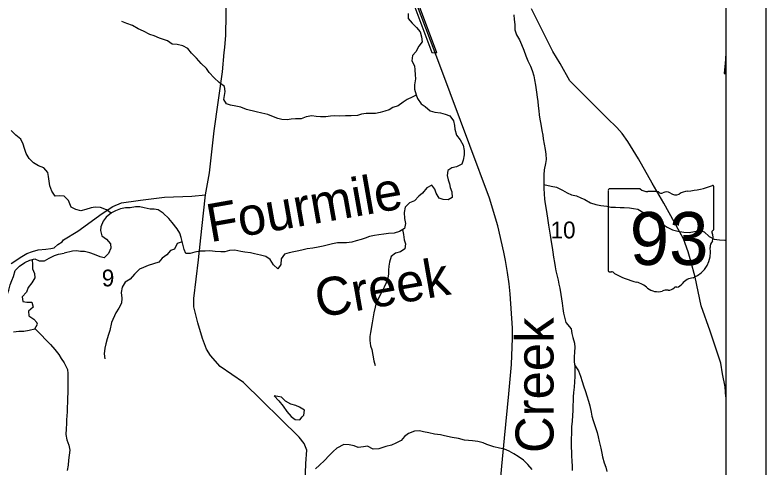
# Model space of a CAD drawing. Extents: x 0 to 34, y 0 to 22.
# Drawn here: x 7.127 to 9, y 17.601 to 18.731 of the extents above; entities that cross this region are included whole.
import ezdxf

# ---------------------------------------------------------------- set-up
doc = ezdxf.new("R2010")
doc.units = 0
for name, color, linetype in [('GM_X_Corporation', 7, 'Continuous'), ('GM_X_County_Road', 7, 'Continuous'), ('GM_X_Major_River', 7, 'Continuous'), ('GM_X_Major_River_Text', 7, 'Continuous'), ('GM_X_Minor_Lake', 7, 'Continuous'), ('GM_X_Minor_River', 7, 'Continuous'), ('GM_X_Minor_River_Text', 7, 'Continuous'), ('GM_X_Rail_Line', 7, 'Continuous'), ('GM_X_Section_Text', 7, 'Continuous'), ('GM_X_State_Location', 7, 'Continuous'), ('GM_X_State_Route', 7, 'Continuous'), ('GM_X_State_Shield', 7, 'Continuous'), ('SH_Data', 7, 'Continuous')]:
    doc.layers.add(name, color=color, linetype=linetype)

msp = doc.modelspace()

# ---------------------------------------------------------------- linework, layer by layer
at = {"layer": 'GM_X_Corporation'}
msp.add_lwpolyline([(7.8422, 19.5022), (8.1668, 18.6372), (8.1793, 18.6363), (7.8577, 19.4956)], dxfattribs=at)
msp.add_lwpolyline([(8.9, 18.5845), (8.9, 18.6278), (8.8955, 18.5848)], close=True, dxfattribs=at)
at = {"layer": 'GM_X_County_Road'}
for points in [[(7.602, 18.2822), (7.6125, 18.3372), (7.6238, 18.442), (7.645, 18.589), (7.649, 18.6371), (7.6503, 18.6497), (7.653, 18.6804), (7.6556, 18.8319), (7.6532, 18.948)], [(7.1177, 18.1111), (7.1444, 18.1289), (7.1563, 18.1363), (7.1707, 18.1413), (7.1846, 18.1452), (7.2043, 18.1471), (7.2167, 18.1482), (7.2244, 18.1498), (7.2341, 18.1583), (7.2444, 18.1648), (7.2479, 18.1697), (7.284, 18.1921), (7.3442, 18.2355), (7.3709, 18.2535), (7.3929, 18.2623), (7.4342, 18.268), (7.4401, 18.2692), (7.4996, 18.2765), (7.5683, 18.279), (7.602, 18.2822)], [(7.851, 17.564), (7.8526, 17.6125), (7.8548, 17.6459), (7.8483, 17.6625), (7.8357, 17.678), (7.6971, 17.8144), (7.6392, 17.8541), (7.6151, 17.8814), (7.6049, 17.8978), (7.5951, 17.9238), (7.5832, 17.9628), (7.5728, 18.0032), (7.5728, 18.024), (7.5845, 18.1204), (7.5932, 18.1984), (7.602, 18.2822)]]:
    msp.add_lwpolyline(points, dxfattribs=at)
at = {"layer": 'GM_X_Major_River'}
for points in [[(8.371, 18.7312), (8.3721, 18.7198), (8.3735, 18.7069), (8.3734, 18.694), (8.3778, 18.6814), (8.3849, 18.6684), (8.3905, 18.657), (8.3957, 18.6426), (8.4012, 18.6292), (8.4064, 18.6167), (8.4124, 18.6033), (8.4169, 18.5919), (8.4209, 18.5786), (8.4223, 18.5691), (8.4249, 18.5558), (8.4278, 18.5383)], [(8.4278, 18.5383), (8.4296, 18.5262), (8.431, 18.5148), (8.432, 18.5042), (8.4334, 18.492), (8.4345, 18.4818), (8.4363, 18.4707), (8.4388, 18.4582), (8.4414, 18.443), (8.4432, 18.4312), (8.4446, 18.4217), (8.4471, 18.4088), (8.4497, 18.3951), (8.4511, 18.3841), (8.4514, 18.3704), (8.4501, 18.3606), (8.4466, 18.3447), (8.4457, 18.3325), (8.446, 18.3215), (8.4459, 18.3105), (8.4462, 18.2984), (8.4465, 18.2847), (8.4479, 18.2711), (8.4497, 18.2597), (8.4522, 18.2456), (8.4536, 18.2353), (8.4551, 18.224), (8.4576, 18.2069), (8.459, 18.1966), (8.4619, 18.1814), (8.4637, 18.1708), (8.4655, 18.1605), (8.467, 18.151), (8.4687, 18.1392), (8.4705, 18.1267), (8.4723, 18.1134), (8.4741, 18.1031), (8.4763, 18.0925), (8.4796, 18.0792), (8.4814, 18.0693), (8.4836, 18.0598), (8.4858, 18.0495), (8.4883, 18.0336), (8.4897, 18.023), (8.4916, 18.0123), (8.4937, 17.9986), (8.4951, 17.9869), (8.4973, 17.977), (8.5006, 17.9641)], [(8.5006, 17.9641), (8.5144, 17.9478), (8.5158, 17.9368), (8.5184, 17.9265), (8.5228, 17.9124), (8.5231, 17.9018), (8.5222, 17.8912), (8.5213, 17.8779), (8.5216, 17.8662), (8.523, 17.8548), (8.5237, 17.8423), (8.5235, 17.829), (8.5227, 17.8158), (8.5214, 17.8025), (8.5202, 17.7896), (8.5193, 17.779), (8.5189, 17.7695), (8.5187, 17.7559), (8.5183, 17.7445), (8.5178, 17.732), (8.5169, 17.7184), (8.5153, 17.7036), (8.5148, 17.6888), (8.5142, 17.6725), (8.5144, 17.6532), (8.5147, 17.6403), (8.515, 17.6304), (8.5157, 17.6194), (8.5163, 17.6046), (8.5166, 17.5948)]]:
    msp.add_lwpolyline(points, dxfattribs=at)
at = {"layer": 'GM_X_Minor_Lake'}
for points in [[(7.7735, 17.7812), (7.7849, 17.769), (7.7958, 17.7554), (7.8049, 17.7425), (7.8155, 17.73), (7.8261, 17.7224), (7.8374, 17.7217), (7.8434, 17.7284)], [(7.8434, 17.7284), (7.8476, 17.733), (7.8495, 17.7452), (7.837, 17.7531), (7.8272, 17.7573), (7.8151, 17.7603), (7.8019, 17.7679), (7.7917, 17.7781), (7.7735, 17.7812)]]:
    msp.add_lwpolyline(points, dxfattribs=at)
at = {"layer": 'GM_X_Minor_River'}
for points in [[(8.1075, 18.7348), (8.1078, 18.7223), (8.1176, 18.7105), (8.1285, 18.6998), (8.1376, 18.6884), (8.1413, 18.6759), (8.1428, 18.6641), (8.1341, 18.6528), (8.1264, 18.6392), (8.1188, 18.6293), (8.1169, 18.6168), (8.1233, 18.6039), (8.124, 18.5937), (8.1255, 18.5815), (8.1258, 18.5713), (8.1235, 18.5569), (8.1231, 18.5459), (8.1272, 18.5318), (8.131, 18.5223), (8.14, 18.5094), (8.1502, 18.5026), (8.1623, 18.4915), (8.1744, 18.4881), (8.188, 18.4865), (8.2001, 18.4834), (8.2118, 18.4792), (8.2205, 18.4671), (8.2235, 18.4553), (8.2242, 18.4458), (8.2283, 18.431), (8.2373, 18.4196), (8.2452, 18.4063), (8.2475, 18.393), (8.2474, 18.382), (8.2451, 18.3688), (8.2413, 18.3585), (8.2284, 18.3521), (8.2167, 18.3495), (8.2064, 18.3427), (8.2045, 18.3302), (8.2075, 18.3196), (8.2105, 18.3101), (8.2127, 18.3006), (8.2168, 18.2896), (8.2172, 18.2759), (8.2073, 18.2699), (8.1948, 18.2703), (8.185, 18.2738), (8.1771, 18.2867), (8.1745, 18.2962), (8.1666, 18.3068), (8.1544, 18.3), (8.1438, 18.2868), (8.1343, 18.2792), (8.1237, 18.2675), (8.1108, 18.2623), (8.1005, 18.2513), (8.0974, 18.238), (8.0989, 18.2232), (8.1011, 18.2107), (8.0981, 18.1986), (8.0859, 18.191), (8.0727, 18.1869), (8.0583, 18.1858), (8.0473, 18.1844), (8.0344, 18.1825), (8.0238, 18.1806), (8.0109, 18.1784), (8.0007, 18.1739), (7.9905, 18.1713), (7.978, 18.1679), (7.9674, 18.1645), (7.9541, 18.1623), (7.9424, 18.1623), (7.9318, 18.1627), (7.9189, 18.1598), (7.9091, 18.1575), (7.8954, 18.1541), (7.8829, 18.1515), (7.8701, 18.1493), (7.8557, 18.1475), (7.8458, 18.1452), (7.8348, 18.143), (7.8223, 18.14), (7.811, 18.1377)], [(8.1275, 18.5312), (8.1177, 18.5262), (8.1052, 18.5198), (8.0954, 18.513), (8.0828, 18.5043), (8.0696, 18.4998), (8.0601, 18.4945), (8.0495, 18.4911), (8.0381, 18.4878), (8.026, 18.4848), (8.0131, 18.4852), (8.0025, 18.4852), (7.9912, 18.4838), (7.9809, 18.4804), (7.9658, 18.4793), (7.951, 18.4793), (7.9374, 18.4786), (7.9238, 18.4791), (7.9136, 18.4787), (7.9026, 18.4772), (7.889, 18.4765), (7.878, 18.4777), (7.867, 18.4792), (7.853, 18.4766), (7.8409, 18.4718), (7.8265, 18.4714), (7.8159, 18.4711), (7.8061, 18.4696), (7.7924, 18.4704), (7.7826, 18.4727), (7.7716, 18.4765), (7.7577, 18.4823), (7.7429, 18.4861), (7.7289, 18.4892), (7.7047, 18.4953), (7.69, 18.5011), (7.6775, 18.503), (7.6643, 18.5057), (7.6544, 18.5088), (7.6477, 18.5198), (7.6492, 18.53), (7.6511, 18.5399), (7.6493, 18.552), (7.6361, 18.5627), (7.6236, 18.5741), (7.6116, 18.5874), (7.6048, 18.5977), (7.5916, 18.6099), (7.5799, 18.6228), (7.5671, 18.6357), (7.5584, 18.6475), (7.5459, 18.6536), (7.5319, 18.6571), (7.5187, 18.6579), (7.5078, 18.6659), (7.4972, 18.6697), (7.4873, 18.6732), (7.4741, 18.6785), (7.4631, 18.682), (7.448, 18.6904), (7.4341, 18.6965), (7.4201, 18.7041), (7.4061, 18.7099), (7.3932, 18.7141)], [(7.25, 18.2789), (7.2391, 18.2801), (7.2277, 18.279), (7.2187, 18.2916), (7.2139, 18.3045), (7.2121, 18.3163), (7.211, 18.3281), (7.2088, 18.3379), (7.1991, 18.3494), (7.1858, 18.3548), (7.173, 18.3621), (7.1625, 18.3731), (7.155, 18.3853), (7.1509, 18.3975), (7.1476, 18.4085), (7.1413, 18.4211), (7.1296, 18.431), (7.1176, 18.4428)], [(8.446, 18.3083), (8.464, 18.3043), (8.4773, 18.3012), (8.4924, 18.2943), (8.5045, 18.2875), (8.515, 18.2825), (8.5275, 18.2798), (8.5381, 18.2748), (8.5479, 18.2703), (8.5623, 18.2622), (8.5755, 18.2584), (8.5884, 18.2561), (8.6031, 18.2538), (8.6133, 18.2518), (8.6247, 18.2518), (8.636, 18.251), (8.6462, 18.2506), (8.6595, 18.2502), (8.6693, 18.2482), (8.6803, 18.2463), (8.6954, 18.2371), (8.7098, 18.2299), (8.7237, 18.2215), (8.7385, 18.212), (8.7536, 18.2017), (8.7668, 18.1952), (8.7804, 18.1917), (8.7952, 18.1894), (8.8088, 18.1886), (8.8217, 18.1912), (8.8353, 18.1934), (8.8455, 18.19), (8.8579, 18.1786), (8.8708, 18.1717), (8.8844, 18.1698), (8.8976, 18.169), (8.9, 18.1696)], [(7.367, 18.2362), (7.3553, 18.2451), (7.3402, 18.2505), (7.3273, 18.2516), (7.3171, 18.2502), (7.3038, 18.246), (7.2913, 18.2427), (7.2792, 18.2461), (7.2675, 18.2515), (7.2604, 18.2685), (7.25, 18.2789)], [(7.811, 18.1377), (7.7996, 18.1344), (7.7912, 18.1226), (7.7897, 18.109), (7.7828, 18.0976), (7.7715, 18.1075), (7.7632, 18.1208), (7.7527, 18.1288), (7.7391, 18.1319), (7.7247, 18.135), (7.7145, 18.1377), (7.7005, 18.1393), (7.6906, 18.1412), (7.6751, 18.1443), (7.6623, 18.1439), (7.6505, 18.1406), (7.6407, 18.1406), (7.6267, 18.1414), (7.6134, 18.143), (7.6017, 18.1419), (7.5888, 18.1415), (7.576, 18.1397), (7.5638, 18.1363), (7.5532, 18.1363), (7.5491, 18.1458), (7.5469, 18.1561), (7.5439, 18.1663), (7.5416, 18.1762), (7.5383, 18.1868), (7.5319, 18.1979), (7.5187, 18.2131), (7.5104, 18.2237), (7.4968, 18.237), (7.484, 18.2447), (7.4738, 18.2462), (7.4639, 18.2466), (7.4492, 18.2497), (7.4386, 18.2524), (7.4276, 18.2528), (7.4144, 18.2498), (7.4026, 18.2499), (7.3905, 18.2476), (7.3776, 18.2424), (7.3681, 18.2371), (7.3549, 18.2269), (7.3469, 18.2167), (7.3412, 18.2027), (7.34, 18.1932), (7.3433, 18.1803), (7.3554, 18.1719), (7.3656, 18.1601), (7.3663, 18.1491), (7.3602, 18.1359), (7.3496, 18.1253), (7.3398, 18.128), (7.3254, 18.1333), (7.3141, 18.1375), (7.3001, 18.1414), (7.2902, 18.1414), (7.2804, 18.1426), (7.2706, 18.1415), (7.2498, 18.1371)], [(8.0936, 18.1958), (8.0957, 18.1834), (8.0976, 18.1705), (8.101, 18.1603), (8.099, 18.1474), (8.0888, 18.1402), (8.0759, 18.1365), (8.0649, 18.1285), (8.0611, 18.1145), (8.0595, 18.1043), (8.0583, 18.0948), (8.0583, 18.085), (8.0571, 18.0747), (8.0526, 18.0626), (8.048, 18.0524), (8.0415, 18.0391), (8.0278, 18.0134), (8.0255, 18.0024), (8.0224, 17.9884), (8.0182, 17.9631)], [(7.5443, 18.165), (7.5314, 18.1607), (7.5245, 18.1471), (7.515, 18.1437), (7.5059, 18.1327), (7.4942, 18.124), (7.4858, 18.1142), (7.4725, 18.1101), (7.4589, 18.1059), (7.4479, 18.1011), (7.4373, 18.0969), (7.4248, 18.0848), (7.4145, 18.072), (7.402, 18.0648), (7.3944, 18.0523), (7.3921, 18.0391), (7.3935, 18.025), (7.3927, 18.0121), (7.3859, 17.9996), (7.3786, 17.9879), (7.3679, 17.9636)], [(7.0856, 17.9641), (7.0857, 17.9796), (7.0854, 17.9898), (7.0892, 18.0031), (7.095, 18.0129), (7.1015, 18.0235), (7.1072, 18.0337), (7.1118, 18.0447), (7.1153, 18.0579), (7.1192, 18.0685), (7.123, 18.0783), (7.1273, 18.0939), (7.1387, 18.1048), (7.152, 18.1138), (7.1638, 18.1198), (7.1767, 18.1227), (7.1873, 18.1177), (7.2005, 18.118), (7.2127, 18.1244), (7.2256, 18.1311), (7.2358, 18.1341), (7.2498, 18.1371)], [(7.1696, 18.1211), (7.1705, 18.108), (7.1709, 18.0977), (7.1757, 18.0859), (7.1764, 18.0757), (7.1687, 18.0632), (7.1599, 18.0515), (7.1561, 18.0394), (7.1454, 18.0281), (7.1465, 18.016), (7.1563, 18.0144), (7.1695, 18.0143), (7.1725, 18.0021), (7.1611, 17.9924), (7.1614, 17.9806), (7.1738, 17.9722), (7.1812, 17.9639)], [(7.1231, 17.9409), (7.1363, 17.9424), (7.1492, 17.9423), (7.1628, 17.9445), (7.1768, 17.9479), (7.1833, 17.9596), (7.1812, 17.9639)], [(7.3679, 17.9636), (7.3638, 17.9442), (7.36, 17.934), (7.3569, 17.923), (7.3539, 17.9105), (7.3512, 17.8999), (7.3496, 17.8859), (7.3514, 17.8738)], [(8.0182, 17.9631), (8.0139, 17.9394), (8.0123, 17.9288), (8.0123, 17.9193), (8.0141, 17.906), (8.0171, 17.8965), (8.0193, 17.8829), (8.0219, 17.8688), (8.0252, 17.8567)], [(7.1771, 17.9484), (7.1926, 17.9331), (7.204, 17.9205), (7.216, 17.9091), (7.2262, 17.8969), (7.2367, 17.884), (7.242, 17.8745), (7.2494, 17.8634)], [(7.2494, 17.8634), (7.2583, 17.8469), (7.2591, 17.8367), (7.259, 17.8226), (7.2586, 17.8132), (7.2593, 17.7995), (7.2585, 17.7897), (7.2584, 17.7753), (7.258, 17.7639), (7.2572, 17.754), (7.2571, 17.7412), (7.2567, 17.7309), (7.2559, 17.7214), (7.2555, 17.712), (7.2551, 17.6987), (7.2542, 17.6847), (7.2568, 17.6718), (7.2617, 17.6581), (7.2635, 17.6456), (7.2623, 17.6335), (7.2608, 17.621), (7.26, 17.6085), (7.2576, 17.5948)], [(8.5226, 17.8585), (8.5324, 17.8438), (8.5373, 17.8301), (8.5417, 17.8168), (8.5451, 17.8062), (8.5499, 17.7921), (8.5533, 17.7808), (8.5574, 17.7678), (8.5604, 17.7565), (8.5641, 17.7405), (8.5659, 17.7307), (8.5689, 17.7196), (8.5726, 17.7094), (8.5786, 17.6897), (8.5816, 17.6786), (8.5838, 17.6676), (8.5879, 17.6506), (8.5905, 17.6384), (8.5927, 17.6289), (8.5968, 17.6145), (8.6002, 17.6031), (8.6027, 17.5921)], [(8.4168, 17.5975), (8.4063, 17.6101), (8.395, 17.6204), (8.3818, 17.6303), (8.3713, 17.6368), (8.3596, 17.6433), (8.3475, 17.6486), (8.3358, 17.651), (8.3211, 17.6544), (8.3041, 17.6602), (8.2943, 17.6637), (8.2814, 17.6671), (8.2682, 17.6691), (8.258, 17.6695), (8.2482, 17.6707), (8.2335, 17.6745), (8.2176, 17.6776), (8.1984, 17.6815), (8.1882, 17.6838), (8.173, 17.6858), (8.1595, 17.6889), (8.1462, 17.6916), (8.1357, 17.6939), (8.1232, 17.6932), (8.1084, 17.6869), (8.0986, 17.6797), (8.0898, 17.6699), (8.0773, 17.6631), (8.0663, 17.6579), (8.0516, 17.6549), (8.0346, 17.6489), (8.0206, 17.6478), (8.0062, 17.6555), (7.996, 17.6544), (7.9828, 17.6526), (7.973, 17.6564), (7.9605, 17.6587), (7.9473, 17.6595), (7.9299, 17.6509), (7.9204, 17.6426), (7.9109, 17.6324), (7.8987, 17.62), (7.8862, 17.6083), (7.8764, 17.5992)]]:
    msp.add_lwpolyline(points, dxfattribs=at)
at = {"layer": 'GM_X_Rail_Line'}
msp.add_lwpolyline([(8.336, 16.2482), (8.3302, 16.398), (8.3141, 16.8322), (8.3089, 16.9635), (8.3066, 17.0299), (8.3031, 17.1252), (8.3035, 17.1977), (8.3057, 17.2297), (8.3479, 17.6756), (8.359, 17.7858), (8.3651, 17.8594), (8.3677, 17.925), (8.3681, 17.9495), (8.3622, 18.0352), (8.3594, 18.06), (8.3556, 18.089), (8.3502, 18.1187), (8.3464, 18.1394), (8.3312, 18.2048), (8.3106, 18.2737), (8.2615, 18.4057), (8.1892, 18.5986), (8.0513, 18.9649)], dxfattribs=at)
at = {"layer": 'GM_X_State_Route'}
msp.add_lwpolyline([(8.9, 17.7787), (8.8985, 17.8037), (8.8919, 17.8359), (8.8874, 17.8627), (8.8611, 17.9425), (8.838, 18.0058), (8.8232, 18.0768), (8.8123, 18.1169), (8.8061, 18.14), (8.7942, 18.1728), (8.7848, 18.1892), (8.7453, 18.2613), (8.7164, 18.3113), (8.682, 18.3718), (8.6553, 18.4151), (8.6411, 18.4353), (8.6281, 18.4501), (8.6038, 18.4732), (8.5111, 18.5665), (8.4869, 18.6098), (8.4685, 18.6396), (8.4149, 18.7463)], dxfattribs=at)
at = {"layer": 'GM_X_State_Shield'}
for p, q in [((8.8703, 18.1973), (8.8703, 18.3019)), ((8.6066, 18.2935), (8.6066, 18.0934)), ((8.6864, 18.297), (8.6092, 18.297)), ((8.8703, 18.1973), (8.8703, 18.1973))]:
    msp.add_line(p, q, dxfattribs=at)
for centre, radius, start, end in [((8.7764, 18.5698), 0.2796, 275.8445, 288.9065), ((8.8674, 18.3024), 0.00294, 351.8621, 97.738), ((8.6096, 18.294), 0.00305, 98.1301, 188.1301), ((8.7048, 18.3202), 0.0296, 231.6195, 271.1119), ((8.7146, 18.1846), 0.1064, 80.4867, 94.9883), ((8.7388, 18.295), 0.00855, 219.7921, 297.1024), ((8.7513, 18.2719), 0.0178, 54.4667, 119.1411), ((8.7743, 18.3036), 0.0214, 233.8562, 294.8282), ((8.812, 18.2359), 0.0563, 97.3462, 120.7689), ((8.8696, 18.1896), 0.00454, 107.944, 210.337), ((8.8407, 18.1763), 0.0273, 340.033, 23.6496), ((8.8672, 18.1969), 0.00314, 289.6038, 7.7341), ((8.8808, 18.1534), 0.0198, 136.8065, 186.9296), ((8.792, 18.1401), 0.0699, 292.3089, 8.9858), ((8.6097, 18.093), 0.00308, 171.9584, 258.3066), ((8.6101, 18.1135), 0.0235, 267.339, 280.6039), ((8.6149, 18.0819), 0.00848, 29.7484, 93.2717), ((8.722, 18.2617), 0.2019, 240.4129, 257.1985), ((8.8215, 18.0372), 0.0383, 94.4031, 142.5768), ((8.6618, 18.0035), 0.0632, 47.1842, 75.836), ((8.773, 18.074), 0.0226, 282.8732, 323.2771), ((8.7301, 18.0809), 0.0401, 230.7004, 286.2918), ((8.7533, 18.0117), 0.0329, 85.6951, 111.2099), ((8.7562, 18.0659), 0.0214, 268.777, 315.5493), ((8.7756, 18.0465), 0.00601, 65.7517, 132.6484)]:
    msp.add_arc(centre, radius, start, end, dxfattribs=at)
at = {"layer": 'SH_Data'}
for p, q in [((9, 21), (9, 14)), ((8.9, 20.9), (8.9, 14.1))]:
    msp.add_line(p, q, dxfattribs=at)

# ---------------------------------------------------------------- texts
at = {"layer": 'GM_X_Major_River_Text'}
msp.add_text('Creek', height=0.09471, rotation=90.0003, dxfattribs=at).set_placement((8.4701, 17.6386))
at = {"layer": 'GM_X_Minor_River_Text'}
for s, rotation, p in [('Fourmile', 9.9988, (7.614, 18.1639)), ('Creek', 9.9989, (7.884, 17.9757))]:
    msp.add_text(s, height=0.0947, rotation=rotation, dxfattribs=at).set_placement(p)
at = {"layer": 'GM_X_Section_Text'}
for s, height, p in [('10', 0.04186, (8.4628, 18.1737)), ('9', 0.0419, (7.3436, 18.0541))]:
    msp.add_text(s, height=height, rotation=0, dxfattribs=at).set_placement(p)
at = {"layer": 'GM_X_State_Location'}
msp.add_text('93', height=0.000189, rotation=0, dxfattribs=at).set_placement((8.6878, 18.1664))
for s in ['s', 'r']:
    msp.add_text(s, height=0.000189, dxfattribs=at).set_placement((8.7355, 18.1802))
at = {"layer": 'GM_X_State_Shield'}
msp.add_text('93', height=0.13184, dxfattribs=at).set_placement((8.6603, 18.1075))

doc.saveas('drawing.dxf')
